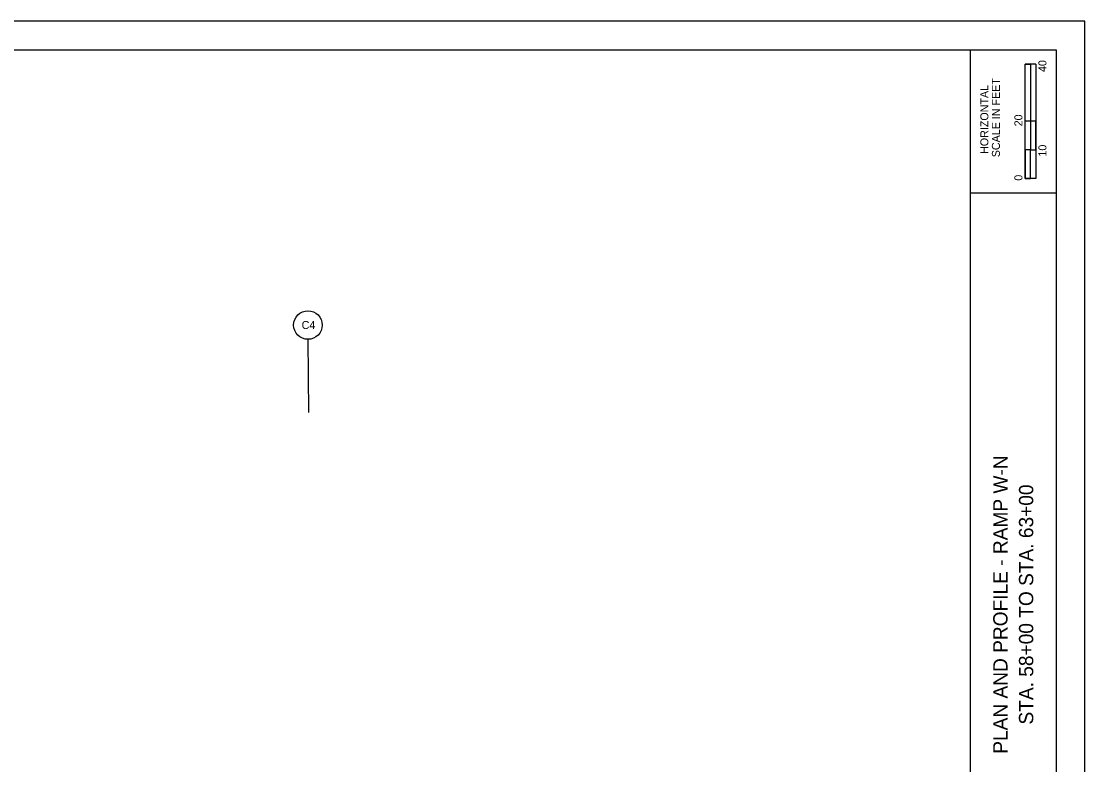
# Model space of a CAD drawing. Extents: x -3.2 to 34, y 0 to 22.
# Drawn here: x 15.41 to 34, y 8.99 to 22 of the extents above; entities that cross this region are included whole.
import ezdxf

# ---------------------------------------------------------------- set-up
doc = ezdxf.new("R2010")
doc.units = 0
for name, color, linetype in [('Default', 7, 'Continuous'), ('SH_Border', 7, 'Continuous'), ('SH_Cut_Line', 7, 'Continuous'), ('SH_Data', 7, 'Continuous')]:
    doc.layers.add(name, color=color, linetype=linetype)

msp = doc.modelspace()

# ---------------------------------------------------------------- linework, layer by layer
at = {"layer": 'Default'}
msp.add_line((20.419, 16.436), (20.428, 15.155), dxfattribs=at)
msp.add_circle((20.418, 16.686), 0.25, dxfattribs=at)
at = {"layer": 'SH_Border'}
for p, q in [((32, 0.5), (32, 21.5)), ((32, 19), (33.5, 19))]:
    msp.add_line(p, q, dxfattribs=at)
msp.add_lwpolyline([(1.5, 21.5), (33.5, 21.5), (33.5, 0.5), (1.5, 0.5)], close=True, dxfattribs=at)
at = {"layer": 'SH_Cut_Line'}
msp.add_lwpolyline([(0, 0), (34, 0), (34, 22), (0, 22)], close=True, dxfattribs=at)
at = {"layer": 'SH_Data'}
for p, q in [((32.957, 19.25), (32.957, 21.25)), ((33.144, 21.25), (32.957, 21.25)), ((32.957, 20.25), (32.957, 21.25)), ((32.957, 21.25), (33.05, 21.25)), ((33.05, 21.25), (33.051, 21.25)), ((33.051, 21.25), (33.051, 20.25)), ((33.144, 21.25), (33.144, 19.25)), ((33.051, 20.25), (32.957, 20.25)), ((33.143, 20.25), (33.05, 20.25)), ((33.05, 20.25), (33.05, 19.75)), ((33.143, 19.75), (33.143, 20.25)), ((33.05, 19.75), (32.957, 19.75)), ((32.957, 19.75), (32.957, 19.25)), ((33.05, 19.25), (33.05, 19.75)), ((33.05, 19.75), (33.143, 19.75)), ((33.144, 19.25), (32.957, 19.25)), ((32.957, 19.25), (33.05, 19.25))]:
    msp.add_line(p, q, dxfattribs=at)

# ---------------------------------------------------------------- texts
at = {"layer": 'Default'}
msp.add_text('C4', height=0.14, dxfattribs=at).set_placement((20.308, 16.616))
at = {"layer": 'SH_Data'}
for s, height, p in [('40', 0.14, (33.33, 21.112)), ('HORIZONTAL', 0.14, (32.315, 19.679)), ('SCALE IN FEET', 0.14, (32.517, 19.621)), ('20', 0.14, (32.91, 20.162)), ('10', 0.14, (33.33, 19.633)), ('0', 0.14, (32.91, 19.211)), ('PLAN AND PROFILE - RAMP W-N', 0.25, (32.65, 9.186)), ('STA. 58+00 TO STA. 63+00', 0.25, (33.1, 9.697))]:
    msp.add_text(s, height=height, rotation=90, dxfattribs=at).set_placement(p)

doc.saveas('drawing.dxf')
